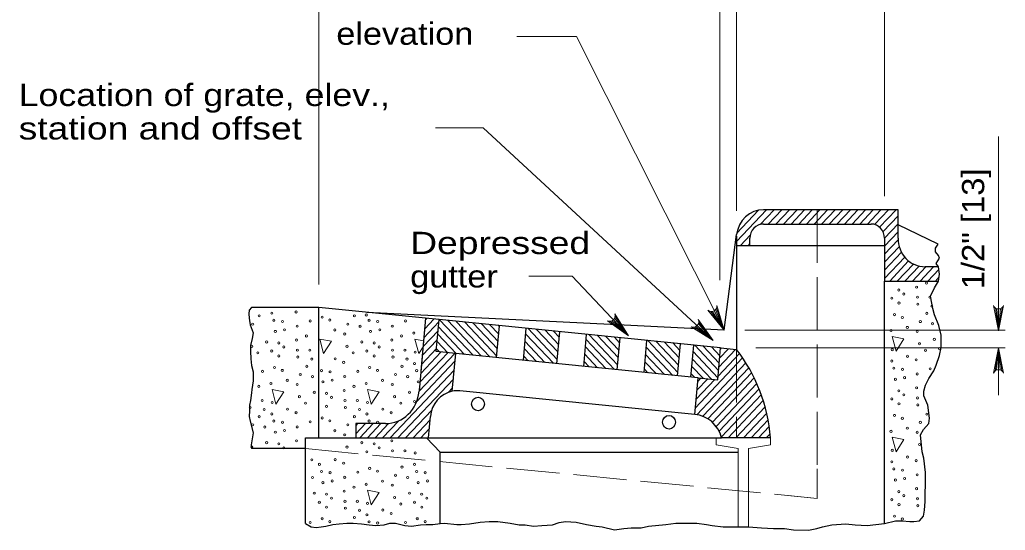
# Model space of a CAD drawing. Extents: x 1352.5 to 1386.5, y 735.9 to 779.9.
# Drawn here: x 1373.58 to 1380.48, y 761.43 to 765.01 of the extents above; entities that cross this region are included whole.
import ezdxf

# ---------------------------------------------------------------- set-up
doc = ezdxf.new("R2010")
doc.units = 0
doc.header["$LTSCALE"] = 0.062
doc.linetypes.add('LONG_DASHED', pattern=[7.5, 6, -1.5])
doc.layers.add('1', color=7, linetype='Continuous', lineweight=13)

msp = doc.modelspace()

# ---------------------------------------------------------------- linework, layer by layer
at = {"layer": '1'}
for p, q in [((1378.48325, 763.18375), (1378.48325, 767.046)), ((1375.673, 763.15467), (1375.673, 766.13667)), ((1378.59942, 763.671), (1378.59942, 766.13667)), ((1379.63783, 763.77275), (1379.63783, 766.13667)), ((1377.05992, 764.89283), (1377.47867, 764.89283)), ((1378.51333, 762.83317), (1377.47867, 764.89283)), ((1380.43642, 762.82958), (1380.43642, 764.19275)), ((1378.59942, 763.45492), (1378.81025, 763.67808)), ((1378.60275, 763.51492), (1378.75367, 763.67467)), ((1378.76683, 763.5755), (1378.86367, 763.67808)), ((1378.82267, 763.57817), (1378.91708, 763.67808)), ((1378.87608, 763.57817), (1378.9705, 763.67808)), ((1378.9295, 763.57817), (1379.02392, 763.67808)), ((1378.98292, 763.57817), (1379.07733, 763.67808)), ((1379.03625, 763.57817), (1379.13067, 763.67808)), ((1379.08967, 763.57817), (1379.18408, 763.67808)), ((1379.14308, 763.57817), (1379.23742, 763.67808)), ((1379.1965, 763.57817), (1379.29083, 763.67808)), ((1379.24992, 763.57817), (1379.34425, 763.67808)), ((1379.30333, 763.57817), (1379.39767, 763.67808)), ((1379.35667, 763.57817), (1379.45108, 763.67808)), ((1379.41008, 763.57817), (1379.50442, 763.67808)), ((1379.46342, 763.57817), (1379.55783, 763.67808)), ((1379.51683, 763.57817), (1379.61125, 763.67808)), ((1379.56708, 763.57483), (1379.66467, 763.67808)), ((1379.60267, 763.55592), (1379.71808, 763.67808)), ((1379.62675, 763.52483), (1379.73225, 763.63658)), ((1379.63775, 763.48), (1379.73225, 763.58)), ((1378.62767, 763.42825), (1378.69642, 763.50108)), ((1379.63783, 763.4235), (1379.73225, 763.52342)), ((1378.68108, 763.42825), (1378.69392, 763.44183)), ((1379.63783, 763.36708), (1379.7325, 763.46717)), ((1379.63783, 763.3105), (1379.7405, 763.41917)), ((1379.63783, 763.25392), (1379.75658, 763.37975)), ((1379.63783, 763.19742), (1379.77883, 763.34667)), ((1379.67333, 763.17842), (1379.80642, 763.31933)), ((1379.72667, 763.17842), (1379.8395, 763.29783)), ((1379.78017, 763.17842), (1379.87917, 763.28325)), ((1379.83358, 763.17842), (1379.92783, 763.27833)), ((1379.887, 763.17842), (1379.98125, 763.27833)), ((1377.14517, 763.21283), (1377.44767, 763.21283)), ((1377.842, 762.79533), (1377.44767, 763.21283)), ((1379.94033, 763.17842), (1380.0175, 763.26008)), ((1379.99375, 763.17842), (1380.01908, 763.20533)), ((1378.41908, 762.96467), (1378.51333, 762.83317)), ((1378.4315, 762.96492), (1378.51333, 762.83317)), ((1378.44217, 762.96875), (1378.51333, 762.83317)), ((1378.45367, 762.97792), (1378.51333, 762.83317)), ((1378.46, 762.98833), (1378.51333, 762.83317)), ((1380.414, 762.98983), (1380.43642, 762.82958)), ((1380.42517, 762.98442), (1380.43642, 762.82958)), ((1380.46125, 762.99175), (1380.43642, 762.82958)), ((1380.45083, 762.98558), (1380.43642, 762.82958)), ((1380.43642, 762.98275), (1380.43642, 762.82958)), ((1376.42125, 762.91717), (1376.37533, 762.40517)), ((1376.42125, 762.91717), (1376.37533, 762.40517)), ((1376.37533, 762.40517), (1376.42125, 762.91717)), ((1376.409, 762.78117), (1376.51375, 762.89208)), ((1376.4145, 762.84358), (1376.47867, 762.91142)), ((1376.42017, 762.90608), (1376.42992, 762.91633)), ((1376.49517, 762.68392), (1376.51517, 762.90775)), ((1376.51783, 762.90742), (1376.75333, 762.658)), ((1376.57675, 762.90158), (1376.81233, 762.65217)), ((1376.63583, 762.89558), (1376.87133, 762.64625)), ((1376.69483, 762.88967), (1376.919, 762.65217)), ((1376.75375, 762.88375), (1376.92367, 762.70383)), ((1376.81283, 762.87783), (1376.92833, 762.75558)), ((1376.87167, 762.872), (1376.93283, 762.80717)), ((1376.93075, 762.866), (1376.9375, 762.85883)), ((1377.71558, 762.89633), (1377.842, 762.79533)), ((1377.72742, 762.9), (1377.842, 762.79533)), ((1377.73675, 762.90658), (1377.842, 762.79533)), ((1377.74525, 762.9185), (1377.842, 762.79533)), ((1377.74858, 762.93008), (1377.842, 762.79533)), ((1378.325, 762.86667), (1378.43583, 762.761)), ((1378.33283, 762.87908), (1378.43583, 762.761)), ((1378.33558, 762.89083), (1378.43583, 762.761)), ((1376.40333, 762.71867), (1376.50825, 762.82958)), ((1376.50617, 762.80658), (1376.63542, 762.66983)), ((1376.51083, 762.85833), (1376.69433, 762.66392)), ((1377.1225, 762.80692), (1377.31658, 762.6015)), ((1377.14008, 762.84492), (1377.34367, 762.62942)), ((1377.19908, 762.839), (1377.34833, 762.681)), ((1377.25808, 762.83308), (1377.35292, 762.73267)), ((1377.31708, 762.82708), (1377.35758, 762.78433)), ((1377.56717, 762.80208), (1377.76692, 762.59058)), ((1377.62617, 762.79617), (1377.7715, 762.64225)), ((1378.30442, 762.85533), (1378.43583, 762.761)), ((1378.31592, 762.85975), (1378.43583, 762.761)), ((1378.65733, 762.83317), (1380.48367, 762.83317)), ((1380.43642, 762.82958), (1380.43642, 762.83317)), ((1376.34642, 762.77192), (1376.37342, 762.6695)), ((1376.40717, 762.76), (1376.34642, 762.77192)), ((1376.39783, 762.65625), (1376.50258, 762.76717)), ((1376.50158, 762.755), (1376.57642, 762.67567)), ((1377.118, 762.75533), (1377.25767, 762.60733)), ((1377.54583, 762.76817), (1377.74367, 762.55858)), ((1377.68517, 762.79025), (1377.77617, 762.69383)), ((1377.74417, 762.78425), (1377.78075, 762.7455)), ((1377.978, 762.76075), (1378.18883, 762.5375)), ((1378.037, 762.75483), (1378.1935, 762.58917)), ((1378.096, 762.74892), (1378.19817, 762.64083)), ((1378.155, 762.743), (1378.20275, 762.6925)), ((1378.307, 762.72817), (1378.47375, 762.55167)), ((1376.37342, 762.6695), (1376.40325, 762.71633)), ((1376.37542, 762.40642), (1376.62525, 762.67092)), ((1376.381, 762.46892), (1376.57642, 762.67575)), ((1376.38667, 762.53133), (1376.52767, 762.68058)), ((1376.39217, 762.59375), (1376.497, 762.70475)), ((1376.497, 762.70333), (1376.51742, 762.68167)), ((1377.11333, 762.70367), (1377.19867, 762.61333)), ((1377.53658, 762.66475), (1377.62575, 762.57042)), ((1377.54117, 762.7165), (1377.68475, 762.5645)), ((1377.96317, 762.66342), (1378.09558, 762.52317)), ((1377.96783, 762.71508), (1378.15467, 762.51725)), ((1378.29592, 762.68333), (1378.46917, 762.50008)), ((1378.366, 762.72217), (1378.47833, 762.60333)), ((1378.425, 762.71633), (1378.483, 762.655)), ((1378.47025, 762.51258), (1378.62008, 762.67125)), ((1378.47583, 762.575), (1378.59333, 762.69942)), ((1378.4815, 762.63758), (1378.5445, 762.70425)), ((1378.48392, 762.71042), (1378.48758, 762.70658)), ((1378.487, 762.69992), (1378.49575, 762.70917)), ((1378.73483, 762.71), (1380.48367, 762.71)), ((1380.41167, 762.5475), (1380.43642, 762.70967)), ((1380.42208, 762.55367), (1380.43642, 762.70967)), ((1380.43642, 762.70967), (1380.43642, 762.37742)), ((1380.43642, 762.5565), (1380.43642, 762.70967)), ((1380.44775, 762.55483), (1380.43642, 762.70967)), ((1380.45892, 762.54942), (1380.43642, 762.70967)), ((1376.35742, 762.33083), (1376.62692, 762.61608)), ((1377.10867, 762.652), (1377.13967, 762.61925)), ((1377.53192, 762.61317), (1377.56675, 762.57633)), ((1377.9585, 762.61183), (1378.03667, 762.52908)), ((1378.29133, 762.63175), (1378.42475, 762.4905)), ((1378.31125, 762.28775), (1378.643, 762.63892)), ((1378.321, 762.2415), (1378.66492, 762.60558)), ((1376.173, 762.079), (1376.62133, 762.55367)), ((1377.95392, 762.56017), (1377.97767, 762.535)), ((1378.28208, 762.52842), (1378.30675, 762.50242)), ((1378.28675, 762.58), (1378.36575, 762.49642)), ((1378.36375, 762.23008), (1378.68575, 762.57108)), ((1378.39992, 762.212), (1378.7055, 762.53542)), ((1376.22642, 762.079), (1376.61567, 762.49125)), ((1378.31683, 762.35025), (1378.44725, 762.48833)), ((1378.32242, 762.41258), (1378.3985, 762.49317)), ((1378.328, 762.47508), (1378.34975, 762.49808)), ((1378.43083, 762.18817), (1378.72425, 762.49883)), ((1378.457, 762.15933), (1378.74183, 762.46092)), ((1376.58158, 762.3985), (1376.61008, 762.42867)), ((1378.47825, 762.12525), (1378.75833, 762.42183)), ((1378.49408, 762.0855), (1378.77358, 762.38142)), ((1378.54133, 762.079), (1378.78767, 762.33983)), ((1376.27983, 762.079), (1376.4635, 762.27342)), ((1378.59475, 762.079), (1378.80033, 762.29667)), ((1378.64817, 762.079), (1378.81158, 762.25208)), ((1375.93283, 762.10742), (1376.00042, 762.179)), ((1375.93283, 762.164), (1375.947, 762.179)), ((1375.95942, 762.079), (1376.05383, 762.179)), ((1376.01283, 762.079), (1376.10725, 762.179)), ((1376.06625, 762.079), (1376.16167, 762.18017)), ((1376.11958, 762.079), (1376.23308, 762.19917)), ((1376.33325, 762.079), (1376.45225, 762.205)), ((1378.70158, 762.079), (1378.82142, 762.206)), ((1376.38667, 762.079), (1376.44667, 762.1425)), ((1378.75492, 762.079), (1378.82942, 762.15792)), ((1378.80833, 762.079), (1378.83583, 762.10808)), ((1376.44, 762.079), (1376.441, 762.08)), ((1378.45675, 762.02908), (1378.45675, 762.079)), ((1378.83858, 762.02908), (1378.83858, 762.079)), ((1378.61225, 762.00408), (1378.45675, 762.02908)), ((1378.61225, 762.00408), (1378.61225, 761.45442)), ((1378.83858, 762.02908), (1378.68308, 762.00408)), ((1378.68308, 762.00408), (1378.68308, 761.45442)), ((1379.16583, 761.65467), (1379.16567, 761.86167)), ((1379.16583, 761.65467), (1378.96167, 761.67458))]:
    msp.add_line(p, q, dxfattribs=at)
at = {"layer": '1', "linetype": 'LONG_DASHED'}
for p, q in [((1379.16583, 763.67808), (1379.16583, 761.65467)), ((1376.42125, 762.91717), (1376.37533, 762.40517)), ((1378.59942, 762.69883), (1378.59942, 762.079)), ((1375.57867, 762.00408), (1379.16583, 761.65467))]:
    msp.add_line(p, q, dxfattribs=at)
at = {"layer": '1', "lineweight": 25}
for p, q in [((1378.78825, 763.57817), (1379.54342, 763.57817)), ((1380.01358, 763.43758), (1379.73225, 763.5725)), ((1378.51333, 762.83317), (1378.601, 763.50375)), ((1378.59942, 763.49192), (1378.59942, 763.42825)), ((1378.59942, 763.42825), (1378.59942, 762.69883)), ((1378.69383, 763.42825), (1379.63783, 763.42825)), ((1379.63783, 763.47825), (1379.63783, 763.17842)), ((1380.01542, 763.27833), (1379.921, 763.27833)), ((1375.673, 762.079), (1375.673, 762.99217)), ((1377.86008, 762.866), (1376.00892, 762.958)), ((1376.42125, 762.91717), (1376.37533, 762.40517)), ((1376.51525, 762.90783), (1376.42125, 762.91725)), ((1378.48792, 762.71), (1376.51525, 762.90783)), ((1376.91808, 762.6415), (1376.93817, 762.86525)), ((1378.51333, 762.83317), (1377.86008, 762.86592)), ((1377.106, 762.62258), (1377.12608, 762.84633)), ((1377.341, 762.599), (1377.36108, 762.82275)), ((1377.52892, 762.58008), (1377.549, 762.80383)), ((1377.76392, 762.5565), (1377.784, 762.78033)), ((1377.95183, 762.53758), (1377.97192, 762.76142)), ((1378.18683, 762.514), (1378.20692, 762.73783)), ((1378.28, 762.50508), (1378.3, 762.72892)), ((1378.33025, 762.5), (1376.63183, 762.67025)), ((1378.30725, 762.24308), (1376.66008, 762.40817)), ((1376.14042, 762.179), (1375.93283, 762.179)), ((1375.57867, 762.079), (1375.93283, 762.079)), ((1375.57867, 761.47942), (1375.57867, 762.079)), ((1376.52267, 761.97908), (1376.42825, 762.079)), ((1376.44092, 762.079), (1378.49583, 762.079)), ((1378.83858, 762.079), (1378.49583, 762.079)), ((1375.57867, 762.00408), (1375.201, 762.00408)), ((1376.52267, 761.97908), (1378.61225, 761.97908)), ((1376.52267, 761.47942), (1376.52267, 761.97908))]:
    msp.add_line(p, q, dxfattribs=at)
at = {"layer": '1'}
for points in [[(1378.43583, 762.761), (1376.82525, 764.25283), (1376.49092, 764.25283)], [(1378.46233, 763.00642), (1378.51333, 762.83317), (1378.39983, 762.97342)], [(1380.47183, 763.00658), (1380.43642, 762.82958), (1380.40108, 763.00658)], [(1377.74608, 762.94817), (1377.842, 762.79533), (1377.69467, 762.89958)], [(1378.33208, 762.90875), (1378.43583, 762.761), (1378.28325, 762.85758)], [(1380.40108, 762.53267), (1380.43642, 762.70967), (1380.47183, 762.53267)], [(1376.14042, 762.179), (1375.93283, 762.179), (1375.93283, 762.079), (1376.42825, 762.079)], [(1376.14042, 762.179), (1375.93283, 762.179), (1375.93283, 762.079), (1376.42825, 762.079)], [(1376.42825, 762.079), (1375.93283, 762.079), (1375.93283, 762.179), (1376.14042, 762.179)]]:
    msp.add_lwpolyline(points, dxfattribs=at)
at = {"layer": '1', "lineweight": 25}
for points in [[(1379.73225, 763.47825), (1379.73225, 763.67808), (1378.78825, 763.67808)], [(1378.59942, 763.42825), (1378.69383, 763.42825), (1378.69383, 763.47825)], [(1380.01542, 763.27833), (1379.99917, 763.30067), (1380.02258, 763.33792), (1380.01483, 763.35858), (1379.99525, 763.38333), (1379.99525, 763.40817), (1380.01358, 763.43758)], [(1375.57867, 761.47942), (1375.619, 761.45567), (1375.65417, 761.4515), (1375.68933, 761.45567), (1375.72058, 761.45983), (1375.77133, 761.47225), (1375.81442, 761.47633), (1375.86908, 761.4805), (1375.91208, 761.4805), (1375.97067, 761.47633), (1376.02542, 761.46808), (1376.07225, 761.46392), (1376.13083, 761.46808), (1376.17, 761.4805), (1376.209, 761.4805), (1376.27542, 761.46392), (1376.32233, 761.45983), (1376.38492, 761.46808), (1376.42392, 761.47225), (1376.47075, 761.47225), (1376.52267, 761.47942), (1376.55283, 761.4805), (1376.63883, 761.47225), (1376.67017, 761.47225), (1376.72875, 761.47633), (1376.80292, 761.48875), (1376.86542, 761.49292), (1376.928, 761.49292), (1377.01392, 761.4805), (1377.07642, 761.46808), (1377.1195, 761.46808), (1377.17808, 761.45983), (1377.23667, 761.46392), (1377.31083, 761.46808), (1377.35775, 761.48467), (1377.40075, 761.49292), (1377.47508, 761.48875), (1377.54925, 761.47225), (1377.61567, 761.45983), (1377.65867, 761.45567), (1377.74467, 761.435), (1377.811, 761.44325), (1377.86183, 761.44742), (1377.93217, 761.44742), (1377.983, 761.45983), (1378.10408, 761.47225), (1378.1745, 761.4805), (1378.26033, 761.4805), (1378.32292, 761.4805), (1378.38933, 761.47225), (1378.42842, 761.46392), (1378.5065, 761.45567), (1378.61225, 761.45442), (1378.68308, 761.45442), (1378.77617, 761.44742), (1378.85825, 761.44325), (1378.93633, 761.44325), (1378.99892, 761.435), (1379.10442, 761.43083), (1379.163, 761.44325), (1379.20208, 761.45567), (1379.2685, 761.46808), (1379.36617, 761.47633), (1379.43258, 761.46808), (1379.51467, 761.46392), (1379.63783, 761.47942), (1379.714, 761.49708), (1379.76083, 761.49708), (1379.8155, 761.49292), (1379.84292, 761.49292), (1379.88192, 761.49708), (1379.90933, 761.53008), (1379.91708, 761.5715), (1379.921, 761.63358), (1379.921, 761.69142), (1379.925, 761.74933), (1379.925, 761.83625), (1379.91325, 761.9355), (1379.9015, 761.981), (1379.88983, 762.10092), (1379.90933, 762.13817), (1379.94842, 762.17958), (1379.95225, 762.21683), (1379.9405, 762.30783), (1379.91325, 762.374), (1379.91325, 762.40708), (1379.925, 762.4485), (1379.94842, 762.494), (1379.98358, 762.54775), (1379.99917, 762.58908), (1380.02258, 762.65525), (1380.03433, 762.71325), (1380.03433, 762.80008), (1380.01875, 762.86625), (1379.98742, 762.94075), (1379.97567, 762.98625), (1379.96017, 763.07317), (1379.98742, 763.131), (1380.01542, 763.17842), (1380.02258, 763.22625), (1380.01542, 763.27833)], [(1379.63783, 761.47942), (1379.63783, 763.17842), (1380.01542, 763.17842)], [(1375.201, 762.99217), (1375.18417, 762.97383), (1375.18167, 762.9475), (1375.18417, 762.91867), (1375.18917, 762.88442), (1375.19158, 762.87125), (1375.2115, 762.816), (1375.2065, 762.77667), (1375.19408, 762.72667), (1375.19408, 762.68717), (1375.19658, 762.632), (1375.20158, 762.58725), (1375.2115, 762.5425), (1375.2115, 762.4795), (1375.204, 762.41892), (1375.20158, 762.39525), (1375.19408, 762.34008), (1375.18667, 762.3085), (1375.18667, 762.26908), (1375.18417, 762.22958), (1375.19158, 762.1955), (1375.2115, 762.11392), (1375.19908, 762.02975), (1375.201, 762.00408)], [(1376.42125, 762.91725), (1375.673, 762.99217), (1375.201, 762.99217)], [(1376.60817, 762.40583), (1376.63183, 762.67025), (1376.49517, 762.68392), (1376.51525, 762.90775)], [(1378.30725, 762.24308), (1378.33025, 762.5), (1378.46792, 762.48617), (1378.48792, 762.71), (1378.59942, 762.69883)], [(1375.93283, 762.179), (1375.93283, 762.079), (1376.42825, 762.079), (1376.44092, 762.079), (1376.45425, 762.22808)]]:
    msp.add_lwpolyline(points, dxfattribs=at)
at = {"layer": '1'}
for points in [[(1375.67892, 762.77192), (1375.70592, 762.6695), (1375.76092, 762.756)], [(1379.69075, 762.78975), (1379.71775, 762.68725), (1379.77275, 762.77375)], [(1375.34517, 762.41858), (1375.37217, 762.31617), (1375.42708, 762.40258)], [(1376.01275, 762.41858), (1376.03967, 762.31617), (1376.09458, 762.40258)], [(1379.69075, 762.08292), (1379.71775, 761.98058), (1379.77275, 762.06708)], [(1376.01275, 761.71183), (1376.03967, 761.6095), (1376.09458, 761.69592)]]:
    msp.add_lwpolyline(points, close=True, dxfattribs=at)
at = {"layer": '1', "linetype": 'LONG_DASHED'}
msp.add_lwpolyline([(1376.14042, 762.179), (1375.93283, 762.179), (1375.93283, 762.079), (1376.42825, 762.079)], dxfattribs=at)
at = {"layer": '1'}
for centre, radius, start, end in [((1378.42442, 763.00253), 0.0382, 229.78621, 5.61234), ((1380.43641, 763.0209), 0.0382, 202.08782, 337.91395), ((1377.71054, 762.93423), 0.0382, 245.49558, 21.32171), ((1378.29731, 762.89302), 0.03822, 248.46129, 24.28742), ((1380.43649, 762.51838), 0.0382, 22.08782, 157.91395)]:
    msp.add_arc(centre, radius, start, end, dxfattribs=at)
at = {"layer": '1', "lineweight": 25}
for centre, major_axis, start_param, end_param in [((1378.78823, 763.47823), (0, 0.19988), 6.2831853, 7.7258806), ((1378.78823, 763.47823), (0, 0.09994), 6.2831853, 7.8539816), ((1379.54343, 763.47823), (0, 0.09994), 4.712389, 6.2831853), ((1379.92103, 763.47823), (0, 0.19988), 1.5707963, 3.1415927), ((1377.78416, 761.98464), (0, 1.1203), 4.7967432, 5.4036465), ((1376.14038, 762.42883), (0, -0.24986), 6.2831853, 7.7593375), ((1376.64224, 762.20922), (0, 0.19988), 0.1815658, 1.4760054), ((1376.64224, 762.20922), (0, 0.19988), 6.1887932, 6.4647511), ((1378.29067, 762.01824), (0, 0.22555), 4.9852966, 6.2052155)]:
    msp.add_ellipse(centre, major_axis=major_axis, ratio=0.944544, start_param=start_param, end_param=end_param, dxfattribs=at)
at = {"layer": '1'}
for centre in [(1379.8624, 763.13596), (1379.93082, 763.16458), (1379.73775, 763.11529), (1379.77318, 763.08731), (1379.8678, 763.06535), (1379.95435, 763.06535), (1379.68785, 763.05869), (1379.73864, 763.02401), (1379.87047, 763.0167), (1379.96876, 763.00239), (1375.25417, 762.93404), (1375.3425, 762.95312), (1375.51283, 762.96172), (1375.69523, 762.92514), (1375.92168, 762.93404), (1376.00537, 762.94074), (1379.7071, 762.94291), (1379.93355, 762.95181), (1375.20883, 762.8765), (1375.35697, 762.90353), (1375.41732, 762.89487), (1375.52006, 762.86242), (1375.61229, 762.89847), (1375.75018, 762.90512), (1375.87634, 762.8765), (1375.96134, 762.86154), (1376.02447, 762.90353), (1376.08483, 762.89487), (1376.18757, 762.86242), (1376.2798, 762.89847), (1379.76206, 762.92289), (1379.88821, 762.89427), (1379.97321, 762.87931), (1375.3677, 762.82526), (1375.43262, 762.83675), (1375.5852, 762.79346), (1375.78528, 762.83545), (1375.85382, 762.80683), (1376.03521, 762.82526), (1376.10013, 762.83675), (1376.25271, 762.79346), (1376.33837, 762.81349), (1379.68273, 762.83125), (1379.79716, 762.85322), (1379.86569, 762.8246), (1375.20255, 762.72097), (1375.30707, 762.75153), (1375.39212, 762.74417), (1375.51678, 762.76484), (1375.87006, 762.72097), (1375.97458, 762.75153), (1376.05963, 762.74417), (1376.18429, 762.76484), (1379.88193, 762.73874), (1379.98645, 762.7693), (1375.24583, 762.67515), (1375.34223, 762.68758), (1375.39301, 762.65289), (1375.42756, 762.7162), (1375.52217, 762.69423), (1375.60873, 762.69423), (1375.91333, 762.67515), (1376.00973, 762.68758), (1376.06052, 762.65289), (1376.09506, 762.7162), (1376.18968, 762.69423), (1376.27624, 762.69423), (1376.34738, 762.67992), (1379.69174, 762.69769), (1379.79899, 762.65093), (1379.92521, 762.69292), (1380.02161, 762.70534), (1375.52484, 762.64559), (1375.58792, 762.58069), (1375.62314, 762.63127), (1375.78712, 762.63316), (1375.84658, 762.60837), (1376.19235, 762.64559), (1376.25543, 762.58069), (1376.29064, 762.63127), (1376.34377, 762.59977), (1379.68813, 762.61754), (1379.85846, 762.62613), (1375.27853, 762.54512), (1375.36147, 762.57179), (1375.41643, 762.55177), (1375.54259, 762.52315), (1375.69072, 762.55018), (1375.75107, 762.54152), (1375.94604, 762.54512), (1376.02898, 762.57179), (1376.08394, 762.55177), (1376.2101, 762.52315), (1376.35823, 762.55018), (1379.70259, 762.56795), (1379.76295, 762.55929), (1379.86569, 762.52684), (1379.95791, 762.56288), (1375.33711, 762.46014), (1375.45153, 762.4821), (1375.52006, 762.45348), (1375.62759, 762.50819), (1375.70146, 762.47191), (1375.76637, 762.4834), (1375.85382, 762.50907), (1376.00462, 762.46014), (1376.11904, 762.4821), (1376.18757, 762.45348), (1376.29509, 762.50819), (1376.36896, 762.47191), (1379.71333, 762.48968), (1379.77824, 762.50117), (1375.25144, 762.44011), (1375.64082, 762.39818), (1375.72588, 762.39082), (1375.85053, 762.41149), (1375.91895, 762.44011), (1376.30833, 762.39818), (1379.73775, 762.40859), (1379.77318, 762.38062), (1379.8624, 762.42926), (1375.27497, 762.34088), (1375.34612, 762.32657), (1375.5363, 762.36762), (1375.57958, 762.3218), (1375.76131, 762.36285), (1375.85593, 762.34088), (1375.94248, 762.34088), (1376.01363, 762.32657), (1376.20381, 762.36762), (1376.24709, 762.3218), (1376.34349, 762.33423), (1379.68785, 762.35199), (1379.73864, 762.31731), (1379.8678, 762.35865), (1379.87047, 762.31), (1375.19109, 762.29224), (1375.28938, 762.27793), (1375.3425, 762.24642), (1375.45337, 762.27981), (1375.51283, 762.25502), (1375.72677, 762.29954), (1375.8586, 762.29224), (1375.95689, 762.27793), (1376.01001, 762.24642), (1376.12087, 762.27981), (1376.18034, 762.25502), (1379.7071, 762.23621), (1379.93355, 762.24511), (1375.20883, 762.1698), (1375.25417, 762.22734), (1375.35697, 762.19683), (1375.41732, 762.18817), (1375.61229, 762.19177), (1375.69523, 762.21844), (1375.75018, 762.19842), (1375.87634, 762.1698), (1375.92168, 762.22734), (1376.02447, 762.19683), (1376.08483, 762.18817), (1379.76206, 762.21619), (1379.88821, 762.18757), (1375.29383, 762.15484), (1375.3677, 762.11856), (1375.43262, 762.13005), (1375.52006, 762.15572), (1375.78528, 762.12875), (1375.85382, 762.10013), (1379.68273, 762.12455), (1379.79716, 762.14652), (1379.86569, 762.1179), (1375.30707, 762.04483), (1375.39212, 762.03747), (1375.51678, 762.05814), (1375.97458, 762.04483), (1376.05963, 762.03747), (1376.18429, 762.05814), (1379.88193, 762.03204), (1375.20255, 762.01427), (1375.42756, 762.0095), (1375.87006, 762.01427), (1376.00973, 761.98088), (1376.09506, 762.0095), (1376.18968, 761.98753), (1376.27624, 761.98753), (1376.34738, 761.97322), (1379.69174, 761.99099), (1375.62314, 761.92458), (1375.67626, 761.89307), (1375.78712, 761.92646), (1375.84658, 761.90167), (1376.34377, 761.89307), (1379.68813, 761.91084), (1379.79899, 761.94423), (1379.85846, 761.91943), (1375.69072, 761.84348), (1375.75107, 761.83482), (1375.94604, 761.83842), (1376.02898, 761.86509), (1376.08394, 761.84507), (1376.25543, 761.87399), (1376.35823, 761.84348), (1376.41858, 761.83482), (1379.70259, 761.86125), (1379.76295, 761.85259), (1379.86569, 761.82014), (1375.62759, 761.80149), (1375.70146, 761.76521), (1375.76637, 761.7767), (1375.85382, 761.80238), (1376.00462, 761.75344), (1376.11904, 761.7754), (1376.2101, 761.81645), (1376.29509, 761.80149), (1376.36896, 761.76521), (1376.43388, 761.7767), (1379.71333, 761.78298), (1379.77824, 761.79447), (1375.64082, 761.69148), (1375.72588, 761.68412), (1375.85053, 761.70479), (1375.91895, 761.73341), (1376.18757, 761.74678), (1376.30833, 761.69148), (1376.39338, 761.68412), (1379.73775, 761.70189), (1379.8624, 761.72256), (1375.67598, 761.62753), (1375.76131, 761.65615), (1375.85593, 761.63418), (1375.94248, 761.63418), (1376.01363, 761.61987), (1376.20381, 761.66092), (1376.24709, 761.6151), (1376.34349, 761.62753), (1376.42882, 761.65615), (1379.68785, 761.64529), (1379.77318, 761.67392), (1379.8678, 761.65195), (1375.72677, 761.59284), (1375.8586, 761.58554), (1375.95689, 761.57123), (1376.12087, 761.57311), (1376.18034, 761.54832), (1376.39427, 761.59284), (1379.73864, 761.61061), (1379.87047, 761.6033), (1375.61229, 761.48507), (1375.69523, 761.51174), (1375.75018, 761.49172), (1375.92168, 761.52064), (1376.01001, 761.53972), (1376.02447, 761.49013), (1376.08483, 761.48147), (1376.2798, 761.48507), (1376.36273, 761.51174), (1376.41769, 761.49172), (1379.7071, 761.52951), (1379.76206, 761.50949)]:
    msp.add_ellipse(centre, major_axis=(0, 0.00756), ratio=0.944544, dxfattribs=at)
at = {"layer": '1', "linetype": 'LONG_DASHED'}
msp.add_ellipse((1376.14038, 762.42883), major_axis=(0, -0.24986), ratio=0.944544, start_param=6.2831853, end_param=7.7593375, dxfattribs=at)
at = {"layer": '1'}
msp.add_ellipse((1376.14038, 762.42883), major_axis=(0, -0.24986), ratio=0.944544, start_param=6.2831853, end_param=7.7593375, dxfattribs=at)
msp.add_ellipse((1376.14038, 762.42883), major_axis=(0, -0.24986), ratio=0.944544, start_param=6.2831853, end_param=7.7593375, dxfattribs=at)
msp.add_ellipse((1376.14038, 762.42883), major_axis=(0, -0.24986), ratio=0.944544, start_param=6.2831853, end_param=7.7593375, dxfattribs=at)
at = {"layer": '1', "lineweight": 25}
for centre in [(1376.78821, 762.31623), (1378.12688, 762.18864)]:
    msp.add_ellipse(centre, major_axis=(0, 0.0476), ratio=0.944544, dxfattribs=at)

# ---------------------------------------------------------------- texts
at = {"layer": '1'}
for s, width, p in [('elevation', 1.15, (1375.79517, 764.83483)), ('Location of grate, elev.,', 1.2, (1373.56892, 764.4055)), ('station and offset', 1.25, (1373.56892, 764.17083)), ('Depressed', 1.25, (1376.31308, 763.36775)), ('gutter', 1.15, (1376.31308, 763.13308))]:
    msp.add_text(s, height=0.156, dxfattribs=dict(at, width=width)).set_placement(p)
at = {"layer": '1', "width": 1.1}
msp.add_text('1/2" [13]', height=0.156, rotation=90, dxfattribs=at).set_placement((1380.33608, 763.12083))

doc.saveas('drawing.dxf')
